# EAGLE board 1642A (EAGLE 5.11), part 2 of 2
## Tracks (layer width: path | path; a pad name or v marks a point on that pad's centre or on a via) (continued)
N$28  (via drill 0.25) (continued)
  Bottom 0.203: J1.86 64.2,43.12 v64.01,43.05
N$29  (via drill 0.25)
  Top 0.152: 53.47,45.97 53.34,45.91 U4.45
  Top 0.203: v63.25,44.96 63.12,44.96 62.1,45.97 53.47,45.97
  Bottom 0.203: J1.90 64.44,44.12 64.26,43.94 63.75,43.94 63.25,44.45 v63.25,44.96
N$30
  Bottom 0.203: U10.5 46.24,70.85 46.36,70.74 | 46.36,70.74 R9.1 | 46.36,70.74 R10.2
N$31  (via drill 0.25)
  Top 0.152: U4.44 53.8,45.42 53.85,45.47
  Top 0.203: v64.01,44.58 63.75,44.32 62.99,44.32 61.85,45.47 53.85,45.47
  Bottom 0.203: J1.92 64.18,44.62 v64.01,44.58
N$32  (via drill 0.25)
  Top 0.152: U3.28 53.29,54.92 54.03,54.92 54.1,54.86
  Top 0.203: v64.01,46.1 63.75,45.85 62.99,45.85 62.61,46.23 62.61,48.39 56.13,54.86 54.1,54.86
  Bottom 0.203: J1.98 64.16,46.12 v64.01,46.1
N$33  (via drill 0.25)
  Top 0.152: U3.29
  Top 0.203: v63.25,46.48 63.25,48.51 56.34,55.42 U3.29
  Bottom 0.203: J1.96 64.42,45.62 64.26,45.47 63.75,45.47 63.25,45.97 v63.25,46.48
N$34  (via drill 0.25)
  Top 0.152: U3.31
  Top 0.203: v63.25,52.96 60.71,52.96 57.23,56.44 U3.31
  Bottom 0.203: J1.102 64.45,52.13 64.26,51.94 63.75,51.94 63.25,52.45 v63.25,52.96
N$35  (via drill 0.25)
  Top 0.152: U3.30 54.03,55.93 54.1,55.88
  Top 0.203: v64.01,52.58 63.75,52.32 60.58,52.32 57.02,55.88 54.1,55.88
  Bottom 0.203: J1.104 64.19,52.63 v64.01,52.58
N$36
  Bottom 0.152: U10.6 45.29,72.08 44.96,71.75 44.96,69.6 C44.2
N$37  (via drill 0.25)
  Top 0.152: 53.26,57.43 U3.33
  Top 0.203: v63.25,54.48 61.09,54.48 58.14,57.43 U3.33
  Bottom 0.203: J1.108 64.43,53.63 64.26,53.47 63.75,53.47 63.25,53.98 v63.25,54.48
N$38  (via drill 0.25)
  Top 0.152: U3.32 53.87,56.92 54.1,56.9
  Top 0.203: v64.01,54.1 63.75,53.85 60.96,53.85 57.91,56.9 54.1,56.9
  Bottom 0.203: J1.110 64.16,54.13 v64.01,54.1
N$39  (via drill 0.25)
  Top 0.152: U3.35 53.29,58.42
  Top 0.203: v63.25,56.01 61.34,56.01 58.93,58.42 53.29,58.42
  Bottom 0.203: J1.114 64.4,55.13 64.26,54.99 63.75,54.99 63.25,55.5 v63.25,56.01
N$40  (via drill 0.25)
  Top 0.152: U3.34 53.87,57.94 53.98,57.91
  Top 0.203: v64.01,55.63 63.75,55.37 61.21,55.37 58.67,57.91 53.98,57.91
  Bottom 0.203: J1.116 64.14,55.63 v64.01,55.63
N$41  (via drill 0.25)
  Top 0.152: U3.39
  Top 0.203: v63.25,57.53 61.6,57.53 58.7,60.43 U3.39
  Bottom 0.203: J1.120 64.38,56.63 64.26,56.52 63.75,56.52 63.25,57.02 v63.25,57.53
N$42  (via drill 0.25)
  Top 0.152: U3.38 53.29,59.92
  Top 0.203: v64.01,57.15 63.75,56.9 61.52,56.9 58.5,59.92 53.29,59.92
  Bottom 0.203: J1.122 64.12,57.13 v64.01,57.15
N$43  (via drill 0.25)
  Top 0.152: 53.29,61.44 U3.41 53.29,61.44
  Top 0.203: v63.25,59.05 61.85,59.05 59.46,61.44 53.29,61.44
  Bottom 0.203: J1.126 64.36,58.13 64.26,58.04 63.75,58.04 63.25,58.55 v63.25,59.05
N$44  (via drill 0.25)
  Top 0.152: 53.3,60.91 U3.40
  Top 0.203: v64.01,58.67 63.75,58.42 61.72,58.42 59.21,60.94 U3.40
  Bottom 0.152: v64.01,58.67 64.1,58.64
  Bottom 0.203: 64.1,58.64 J1.128
N$45  (via drill 0.25)
  Top 0.152: U3.43
  Top 0.203: v63.25,60.45 62.23,60.45 60.25,62.43 U3.43
  Bottom 0.203: J1.132 64.33,59.64 64.26,59.56 63.63,59.56 63.25,59.94 v63.25,60.45
N$46  (via drill 0.25)
  Top 0.152: U3.42
  Top 0.203: v64.01,60.2 63.63,59.82 62.1,59.82 60,61.93 U3.42
  Bottom 0.152: v64.01,60.2 64.07,60.14
  Bottom 0.203: 64.07,60.14 J1.134
N$47  (via drill 0.25)
  Top 0.152: R52.1 71.44,31.75 71.63,31.75 71.75,31.88 v72.52,31.88
  Bottom 0.152: J1.41 72.28,32.12 v72.52,31.88
N$48
  Top 0.508: 14.68,53.29 15.47,53.29
N$49  (via drill 0.25)
  Top 0.152: v22.22,51.44 U2.E5
  Bottom 0.152: R28.2 22.61,51.44 v22.22,51.44
N$50  (via drill 0.25)
  Top 0.152: 53.29,63.45 U3.45
  Top 0.203: v63.25,61.98 62.48,61.98 61.01,63.45 53.29,63.45
  Bottom 0.203: J1.138 64.31,61.14 64.26,61.09 63.63,61.09 63.25,61.47 v63.25,61.98
N$51  (via drill 0.25)
  Top 0.152: U3.44
  Top 0.203: v64.01,61.72 63.63,61.34 62.36,61.34 60.76,62.94 U3.44
  Bottom 0.152: v64.01,61.72 64.09,61.64
  Bottom 0.203: 64.09,61.64 J1.140
N$52
  Bottom 0.152: U5.8 60.69,70.09 61.09,70.48 61.85,70.48 | 61.85,70.48 R49.1 | SJ2.1 61.85,70.48
N$53
  Bottom 0.813: R46.2 57.02,49.02 57,49.05 R45.2
N$54
  Bottom 0.813: R45.1 60.09,52.83 60.2,52.71 60.09,52.81 R44.1
N$55
  Bottom 0.813: 57.15,57.15 R44.2 R43.2
N$56
  Bottom 0.203: J1.38 66.63,25.61 67.06,26.04 69.6,26.04 70.03,25.6 J1.37
N$57
  Bottom 0.813: R43.1 51.29,57.02 51.31,57.02 51.29,57.05 R42.1
N$58
  Bottom 0.813: 57.15,61.6 R37.2 R42.2
N$59  (via drill 0.25)
  Top 0.203: R53.1 65.15,25.9 64.9,26.16 64.77,26.29 v64.77,26.92
  Bottom 0.203: J1.40 65.19,26.16 64.77,26.16 v64.77,26.92
N$60
  Top 0.127: 44.19,54.93 37.65,54.93 35.56,57.02 30.23,57.02 29.97,56.77 | U2.J11 29.97,56.39
  Top 0.152: R30.2 44.17,54.92 44.19,54.93 U3.21 | 29.97,56.39 29.97,56.77
N$61
  Bottom 0.152: U5.5 56.53,70.09 56.52,70.1 55.88,70.1 R48.2 R47.1 55.88,69.21
N$62  (via drill 0.25)
  Top 0.203: R54.2 65.28,65.79 65.53,66.04 v66.55,66.04
  Bottom 0.203: J1.156 66.15,65.64 v66.55,66.04
N$63
  Top 0.127: 44.07,55.37 37.72,55.37 35.69,57.4 29.97,57.4 29.59,57.02 29.59,56.39 29.21,56.01
  Top 0.152: R30.1 44.17,55.4 | U3.20 44.21,55.43 R30.1 | 44.07,55.37 44.12,55.42 R30.1 | U2.J10 29.21,56.01
N$64
  Bottom 0.152: C10.2 54.74,70.23 55.12,70.61 57.4,70.61 57.4,70.59 U5.6
N$65  (via drill 0.25)
  Top 0.127: v24.13,59.44 28.07,63.37 42.14,63.37 42.6,62.92 43.41,62.92 R17.2
  Top 0.152: R17.2 43.43,62.92 43.45,62.93 U3.5 | U2.E6 v24.77,51.44
  Route2 0.127: v24.77,51.44 24.77,52.07 23.88,52.96 23.88,58.55 24.13,58.8 v24.13,59.44
N$66  (via drill 0.25)
  Top 0.127: v24.77,58.8 24.77,59.69 25.02,59.94 25.27,59.94 28.32,62.99 | 41.78,62.99 42.42,62.36 44.32,62.36 | U2.F6 24.13,52.2 24.38,52.32 24.64,52.32 25.02,52.71 v26.04,52.71
  Top 0.152: U3.6 44.27,62.43 44.25,62.41 44.22,62.43 R18.1 44.25,62.43 44.32,62.36 | 28.32,62.99 41.78,62.99
  Route2 0.127: 24.77,54.74 v24.77,58.8
  Route2 0.152: v26.04,52.71 24.64,52.71 24.26,53.09 24.26,54.23 24.77,54.74
N$68  (via drill 0.25)
  Top 0.127: v25.27,59.44 28.45,62.61 41.53,62.61 42.29,61.85 44.07,61.85
  Top 0.152: 44.2,61.95 44.17,61.98 | 44.2,61.95 R18.2 44.15,61.93 44.07,61.85 | U3.7 44.22,61.93 44.2,61.95 | U2.G6 v24.77,53.98
  Route2 0.127: 25.4,54.61 25.4,59.31 v25.27,59.44
  Route2 0.152: v24.77,53.98 25.4,54.61
N$69  (via drill 0.25)
  Top 0.127: U2.D10 29.72,49.02 38.61,49.02 39.37,48.26 v39.37,46.48 | R34.1 44.2,42.93 44.07,42.93 43.94,42.8 39.75,42.8 v39.62,42.93
  Top 0.152: R34.1 | R34.1 U4.10 | R34.1 44.17,42.93
  Route2 0.127: v39.37,46.48 39.37,43.18 v39.62,42.93
N$70
  Top 0.127: 44.2,60.43 40.77,60.45 40.28,60.94 29.18,60.94 25.15,56.9 25.15,56.64 24.89,56.39 24.89,55.12
  Top 0.152: R20.1 44.2,60.43 44.22,60.4 44.25,60.43 U3.10 | U2.H7 24.89,55.12
N$71
  Top 0.127: R35.1 42.95,40.92 42.8,40.77 31.88,40.77 31.5,40.39 29.84,40.39 29.59,40.64 29.59,44.96 29.72,45.09 29.72,46.23 29.46,46.48 29.46,46.74 U2.B10
  Top 0.152: R35.1 43.46,40.92 43.47,40.91 U4.14
N$73  (via drill 0.25)
  Top 0.127: U2.D8 25.91,48.77 25.91,44.58 v25.53,44.2 | v31.75,44.2 32.51,44.2 34.04,45.72 43.18,45.72 43.31,45.85 43.43,45.85 R31.1
  Top 0.152: R31.1 43.46,45.92 43.48,45.91 U4.4
  Route2 0.127: v25.53,44.2 v31.75,44.2
N$74
  Top 0.127: R21.1 39.6,58.45 38.1,59.94 29.34,59.94 25.91,56.52 25.91,53.72 26.04,53.59 26.42,53.59 U2.G8
  Top 0.152: R21.1 43.46,58.42 43.47,58.43 U3.14
N$75
  Top 0.127: U2.A10 29.21,40.39 29.59,40.01 31.75,40.01 32.13,40.39 43.43,40.39
  Top 0.152: 43.38,40.41 43.36,40.44 | 43.38,40.41 R35.2 43.43,40.39 | U4.15 43.39,40.41 43.38,40.41
N$76
  Top 0.127: 44.2,57.4 44.07,57.28 38.48,57.28 36.83,58.93 29.34,58.93 27.56,57.15 27.56,56.64 U2.J8
  Top 0.152: U3.16 44.15,57.43 R22.1 44.2,57.4
N$77
  Top 0.127: 44.16,56.93 38.45,56.93 36.7,58.67 29.46,58.67 27.94,57.15 U2.J9
  Top 0.152: R22.2 44.15,56.92 44.16,56.93 U3.17
N$78
  Top 0.127: 43.43,56.39 38.1,56.39 36.32,58.17 29.59,58.17 28.45,57.02 28.45,55.25 28.57,55.12 28.57,53.98 U2.G10
  Top 0.152: R23.1 43.43,56.39 45.74,56.39 U3.18
N$81  (via drill 0.25)
  Top 0.127: U2.C8 26.16,47.75 v26.16,43.69 | v32.26,43.69 32.38,43.82 32.51,43.82 34.16,45.47 43.18,45.47 43.43,45.34 R31.2
  Top 0.152: R31.2 43.42,45.41 | 43.42,45.41 U4.5 | 43.42,45.41 43.41,45.42
  Route2 0.127: v26.16,43.69 v32.26,43.69
N$86
  Top 0.152: U4.19 R39.2
N$88
  Top 0.152: R38.1 44.17,39.9 44.17,39.91 U4.16
N$93
  Top 0.127: 43.43,55.88 38.1,55.88 36.2,57.79 29.72,57.79 28.7,56.77 28.7,55.5 28.96,55.25 29.59,55.25 29.84,54.99 29.84,53.98 U2.G11
  Top 0.152: U3.19 43.44,55.93 43.43,55.93 R23.2 43.43,55.88
N$95
  Top 0.127: 43.34,60.93 41.66,60.96 41.05,61.57 29.05,61.57 24.51,57.02 24.51,56.52 24.64,56.39 24.64,55.25 24.51,55.12
  Top 0.152: R19.2 43.33,60.94 43.34,60.93 U3.9 | U2.H6 24.51,55.12
N$99
  Top 0.127: 25.4,55.93 25.53,56.06 25.53,56.77 29.34,60.58 40.13,60.58 40.77,59.94 R20.2
  Top 0.152: 44.13,59.93 44.15,59.94 R20.2 | 44.13,59.93 U3.11 | 44.13,59.93 44.12,59.92 | U2.J7 25.4,55.93
N$100
  Top 0.127: U2.G9 27.3,53.98 26.42,53.98 26.16,54.23 26.16,56.39 29.34,59.56 37.97,59.56 39.62,57.91 43.31,57.91 43.33,57.94 R21.2
  Top 0.152: 43.41,57.94 43.38,57.96 | R21.2 43.41,57.94 | U3.15 43.41,57.93 43.41,57.94
N$101
  Top 0.127: U2.J6 24.13,57.15 28.83,61.98 41.15,61.98 41.66,61.47 43.43,61.47
  Top 0.152: U3.8 43.45,61.43 R19.1 43.43,61.47 43.43,61.34
N$105  (via drill 0.25)
  Top 0.127: U2.D9 27.18,48.77 27.18,43.56 v26.8,43.18 | v31.75,43.18 32.89,43.18 33.27,43.56 37.34,43.56 38.48,44.7 43.94,44.7 44.07,44.83 44.2,44.83 R32.1
  Top 0.152: 44.1,44.91 44.12,44.88 R32.1 | 44.1,44.91 U4.6 | 44.1,44.91 44.09,44.91
  Route2 0.127: v26.8,43.18 v31.75,43.18
N$106  (via drill 0.25)
  Top 0.127: U2.C9 27.43,47.75 v27.43,42.67 | v32.26,42.67 32.77,42.67 33.4,43.31 37.47,43.31 38.61,44.45 43.94,44.45 44.07,44.32 44.12,44.37 R32.2
  Top 0.152: U4.7 44.23,44.41 R32.2
  Route2 0.127: v27.43,42.67 v32.26,42.67
N$107  (via drill 0.25)
  Top 0.127: U2.B9 28.57,46.36 v28.57,42.16 | v32.77,42.16 37.08,42.16 38.74,43.82 43.23,43.82 43.36,43.94
  Top 0.152: U4.8 43.5,43.91 43.49,43.89 43.46,43.92 R33.1 43.33,43.92 43.36,43.94
  Route2 0.152: v28.57,42.16 v32.77,42.16
N$108  (via drill 0.25)
  Top 0.127: v27.94,41.66 U2.A9 | v32.26,41.66 32.94,41.66 33.2,41.91 37.21,41.91 38.86,43.56 43.18,43.54 43.31,43.41
  Top 0.152: 43.38,43.41 43.36,43.43 | 43.38,43.41 R33.2 43.31,43.41 | U4.9 43.39,43.41 43.38,43.41
  Route2 0.152: v27.94,41.66 v32.26,41.66
N$109  (via drill 0.25)
  Top 0.127: U2.C10 29.72,48.77 38.48,48.77 39.12,48.13 39.12,47.37 v38.86,47.12 | R34.2 44.2,42.42 v38.99,42.42
  Top 0.152: 44.11,42.41 44.12,42.39 R34.2 | 44.11,42.41 U4.11 | 44.11,42.41 44.09,42.42
  Route2 0.127: v38.86,47.12 38.86,42.55 v38.99,42.42
N$114
  Top 0.152: 44.14,39.41 44.15,39.4 R38.2 | 44.14,39.41 U4.17 | 44.14,39.41 44.09,39.45
N$124
  Top 0.152: 44.2,37.41 44.17,37.44 | R40.2 44.2,37.41 | U4.21 44.2,37.41
N$126
  Top 0.152: R39.1 43.43,38.89 43.45,38.91 U4.18
N$131
  Top 0.152: R40.1 44.17,37.9 44.18,37.91 U4.20
OEL  (via drill 0.25)
  Top 0.127: U2.C11 29.84,47.62 29.84,46.74 30.23,46.36 30.73,46.36 30.99,46.1 30.99,41.78 v30.23,41.02 | v30.23,39.37 30.23,36.96 29.97,36.7 26.04,36.7 25.91,36.58 25.91,34.67 26.92,33.66 J3.3
  Bottom 0.127: v30.23,39.37 v30.23,41.02
OUT-ENABLE  (via drill 0.38)
  Top 0.203: U4.13 44.57,41.41 v44.32,41.66 | U3.13 44.57,58.93 v44.32,59.18
  Bottom 0.203: v44.32,41.66 45.59,41.66 | 45.59,41.66 45.85,41.91 45.85,58.67 45.34,59.18 v44.32,59.18 | 45.59,41.66 45.85,41.4 48.01,41.4 51.94,37.47 51.94,34.29 52.9,33.34 R24.2 62.23,33.34 SJ1.2 62.25,32.62 J1.44
OVDD  (via drill 0.25, 0.3)
  Top 0.254: v24.77,48.9 U2.D7
  Top 0.61: U2.H11 v31.11,53.98 U2.G12 v32.38,53.34 | v27.3,55.25 U2.H9
  Route2 0.305: v27.3,55.25 27.3,53.09 26.67,52.45 26.67,51.69 27.18,51.18 27.18,50.67 26.67,50.17 25.78,50.17 25.4,49.78 U2.D7 v24.77,48.9
  Bottom 0.61: v27.3,55.25 30.86,55.25 30.86,54.23 v31.11,53.98 U2.G12 v32.38,53.34
  Bottom 0.813: 30.86,55.25 R14.2
PWR-ON
  Bottom 0.203: J1.42 62.25,32.12 SJ1.1 R29.1
RF
  Top 0.406: 16.21,53.29 C42.1 | L1.2 15.58,53.28 15.57,53.29
  Top 0.508: C42.1 16.31,53.34 U2.G1 | 15.57,53.29 16.21,53.29
SCL  (via drill 0.25)
  Top 0.203: R25.1 59.5,24.26 59.69,24.26 59.82,24.13 v60.45,24.13
  Bottom 0.203: v60.45,24.13 60.51,24.07 U1.6 65.09,24.07 65.15,24.13 65.15,24.11 J1.34
SDA  (via drill 0.25)
  Top 0.203: v60.45,24.89 60.33,25.02 59.05,25.02 58.42,24.38 58.42,24.32 R26.1
  Bottom 0.203: v60.45,24.89 60.62,24.72 U1.5 63.46,24.72 63.88,25.15 67.06,25.15 67.44,25.53 69.21,25.53 69.6,25.15 72.26,25.15 72.52,24.89 72.52,24.26 72.39,24.13 71.5,24.13 71.37,24 71.41,24 J1.33
SENSE
  Top 0.127: 22.22,43.43 23.5,44.7 23.5,52.45 23.75,52.71 24.51,52.71 24.89,53.09 25.27,53.09 U2.G7
  Top 0.152: 22.22,43.43 22.22,37.21 21.72,36.7 16.26,36.7 16.03,36.47 16.03,35.71 15.98,35.66 J4.2
  Top 0.203: J4.4 16,33.66 J4.4 J4.6
  Bottom 0.203: J4.2 15.98,35.66 15.98,33.68 16,33.66 J4.4
  Bottom 0.254: C19.1 17.53,31.62 17.49,31.66 J4.6
SHDN  (via drill 0.25)
  Top 0.127: U2.B11 31.24,46.23 31.24,41.15 v31.11,41.02 | v31.11,39.37 30.61,38.86 30.61,36.83 29.97,36.2 29.97,34.67 28.96,33.66 J3.4
  Bottom 0.127: v31.11,39.37 v31.11,41.02
VCC1  (via drill 0.3, 0.81)
  Top 0.152: U2.E1 v17.14,50.8 15.98,49.64 15.98,39.77 15.98,39.78 15.6,39.4 5.89,39.4 5.66,39.17 5.66,36.48 J6.1
  Top 0.406: U2.F2 v19.05,51.44 U2.E2 v18.41,50.8 U2.E1 v17.14,50.8
  Bottom 0.203: 34.86,69.15 R15.2 | R15.2 34.86,69.15 | 34.86,69.15 34.8,69.09
  Bottom 0.406: U2.E2 23.5,50.8
  Bottom 0.508: v17.14,50.8 v18.41,50.8 U2.E2 v19.05,51.44 | 23.5,50.8 23.88,51.18 23.88,56.26 26.04,58.42 26.04,59.56 27.43,60.96 32.64,60.96 33.27,61.6 v33.27,65.91 34.93,67.56 34.93,69.34 R15.2
VCC2  (via drill 0.3, 0.81)
  Top 0.152: R36.2 14.91,37.72 16.36,39.17 16.38,46.69 16.69,46.99 v17.14,46.99
  Top 0.406: U2.B2 v18.41,46.99 U2.B1 v17.14,46.99
  Bottom 0.406: v17.14,46.99 v18.41,46.99 19.56,46.99 19.68,46.86 19.68,44.45 19.81,44.32 23.24,44.32 23.5,44.58 23.5,48.9 24.13,49.53 25.15,49.53 25.4,49.78 25.4,50.55 25.27,50.67 25.27,51.05 25.4,51.18 25.4,51.69 25.27,51.82 25.27,53.09
  Bottom 0.508: 25.27,53.09 25.53,53.34 25.53,56.39 26.8,57.66 26.8,59.18 27.69,60.07 37.34,60.07 38.48,61.21 v38.48,65.91 R3.2 38.48,67.82
VCM
  Bottom 0.254: R11.1 R7.2 23.68,33.13 arc-90 23.67,33.15 arc-90 23.52,33 22.94,33 22.61,32.66 14.96,32.66 J4.3
VDD  (via drill 0.3, 0.81)
  Top 0.254: J4.1 14.86,34.67 17.4,34.67 18.41,35.69 19.94,35.69 | J3.2 J3.1 27.94,35.66 27.94,33.02 27.56,32.64 21.46,32.64 20.95,33.15 20.95,34.67 19.94,35.69 | 19.94,35.69 19.95,35.67 J2.1
  Top 0.305: U2.D11 29.84,50.17 27.3,50.17 U2.E8
  Top 0.406: v26.04,50.8 v26.04,50.17
  Top 0.61: U2.E7 v26.04,50.8 U2.E8
  Bottom 0.152: 26.92,35.66 26.92,35.56 | J3.1 26.92,35.66 | 26.92,35.66 26.92,35.69
  Bottom 0.254: R6.1 20.2,37.35 19.95,37.1 J2.1
  Bottom 0.305: v24.77,40.64 24.77,39.12 26.92,36.96 26.92,35.69
  Bottom 0.356: v24.77,40.64 24.77,47.62
  Bottom 0.406: 26.54,53.21 26.67,52.96 26.67,51.44 v26.04,50.8 26.04,48.9 24.77,47.62
  Bottom 0.61: 26.54,53.21 26.54,56.01 27.56,57.02 27.62,57.09 R13.2
VIN
  Bottom 0.203: R49.2 61.85,68.96
  Bottom 0.406: C8.1 61.66,64.45 60.2,62.99 60.2,61.6 R37.1
  pour Bottom (no thermals): 59.99,69.14 59.99,68.55 60.91,68.55 61.14,68.33 61.14,66.55 61.16,66.52 61.16,64.97 62.15,64.97 62.15,69.14
VROM  (via drill 0.25)
  Top 0.203: v60.45,22.61 60.58,22.61 | C27.1 59.65,22.61 v60.45,22.61 | v60.45,22.61 61.41,22.61 R27.2 61.47,22.61 69.34,22.61 70.1,23.37 70.1,32.13 70.55,32.57 R51.1 R52.2 71.37,32.64 | C27.1 59.44,22.48 R25.2 59.38,23.37 58.17,23.37 R26.2 | C27.1 59.56,22.48
  Bottom 0.203: U1.8 60.62,22.77 v60.45,22.61
WP  (via drill 0.25)
  Top 0.203: R27.1 61.4,23.5 61.34,23.5 61.21,23.37 v60.45,23.37
  Bottom 0.203: U1.7 60.64,23.42 v60.45,23.37 60.07,23.37 59.82,23.11 J8.1

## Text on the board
Top: 4
Route2: 5
Route3: 6
Bottom: 7
tPlace: 2
bPlace: 9
tNames: +5V | GND | +3.3V | LO | DC1642A LTM9003IV- | PRE-DISTORTION RECEIVER | +2.5V | [LVDS OUTPUT] | www.linear.com | (408) 432-1900 | RF | MIXER_EN | AMP_EN | SENSE | MODE | OE# | SHDN | VDD | ON | ON | VDD | 2/3 | OFF | OFF | 1.25V | ON | ON | OFF | EXT | OFF | GND | 1/3 | EXT | GND | ENCODE | CLK | REF
bNames: LTC CONFIDENTIAL | FOR CUSTOMER USE ONLY | VCC1 | VCC2 | VDD | hsmc
tStop: 3
bStop: 8
tCream: 1
bCream: 10
bRestrict: BACK | REV A1
Measures: NO TABS HERE | 0.350 | FIDUCIAL, 3X | 2.400 | 2.900 | 2.900 | NO TABS HERE | 3.100 | 0.050 | 0.100 | 0 | ORIGIN | NO TABS HERE | 2.400 | 0.067" TOOLING HOLE | 0.050 | UNPLATED, 2X | 0 | 2.925
Document: DC1642A | A | LM9003 PRE-DISTORTION RCVR | E.TRELEWICZ | 10 | 24NOV09
Reference: A1 | INITIAL RELEASE | 24NOV09 | 1 | 0.009" | 1 | 0.039" | 1 | 0.009" | 1 | DC1642 | REV A | DRILL LEGEND | SYM SIZE QTY TOLERANCE PLTD | .010 | 33 | +0/-.010 | YES | .012 | 545 | +0/- .012 | YES | .015 | 540 | +/- .003 | YES | LTM9003 | .032 | 32 | +/- .003 | YES | E.TRELEWICZ | .066 | 5 | +/- .003 | YES | PRE-DISTORTION RECEIVER, LVDS OUTPUT | .067 | 2 | +.004/-0 | NO | E.TRELEWICZ | .188 | 4 | +/- .003 | YES | E.TRELEWICZ | DC1642 | A | 1 | 1
tDocu: DC1642 | A | LM9003 PRE-DISTORTION RCVR | E.TRELEWICZ | 24NOV09
bDocu: LM9003 PRE-DISTORTION RCVR | DC1642 | A | E.TRELEWICZ | 24NOV09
